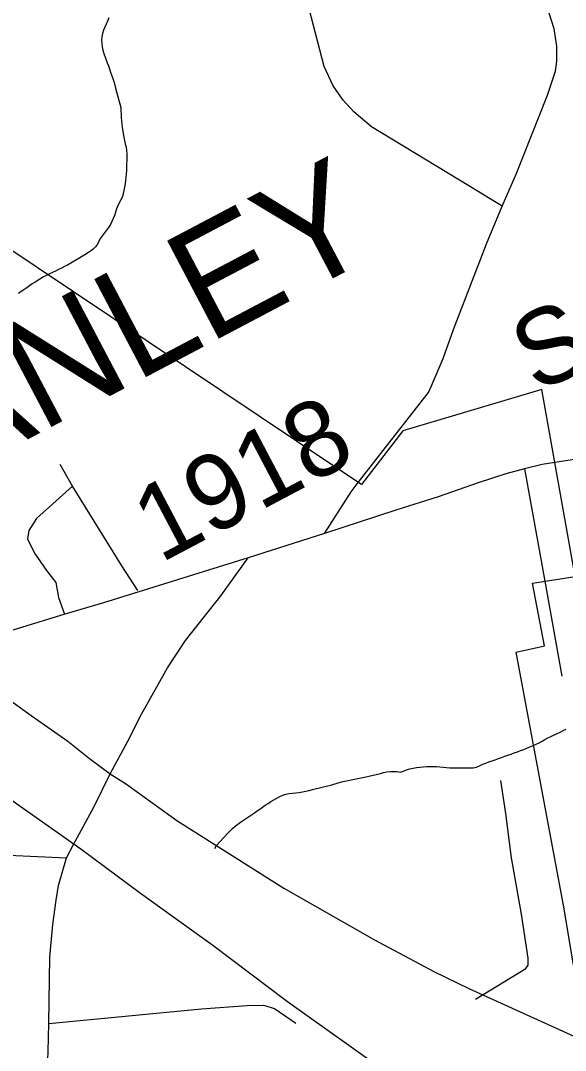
# Model space of a CAD drawing. Extents: x 1379448 to 1382868, y 593769 to 596827.
# Drawn here: x 1379829.3 to 1379935.9, y 595296.5 to 595497.8 of the extents above; entities that cross this region are included whole.
import ezdxf

# ---------------------------------------------------------------- set-up
doc = ezdxf.new("R2010")
doc.units = 0
for name, color, linetype in [('Old_Level_11', 7, 'Continuous'), ('Old_Level_29', 7, 'Continuous'), ('Old_Level_32', 7, 'Continuous'), ('Old_Level_35', 7, 'Continuous'), ('Old_Level_44', 7, 'Continuous'), ('Old_Level_48', 7, 'Continuous'), ('Old_Level_49', 7, 'Continuous'), ('Old_Level_59', 7, 'Continuous'), ('Old_Level_62', 7, 'Continuous'), ('Old_Level_8', 7, 'Continuous'), ('Old_Level_9', 7, 'Continuous')]:
    doc.layers.add(name, color=color, linetype=linetype)

msp = doc.modelspace()

# ---------------------------------------------------------------- linework, layer by layer
at = {"layer": 'Old_Level_29'}
for points in [[(1379811.94, 595374.69), (1379823.59, 595367.52), (1379831.41, 595361.9), (1379838.57, 595356.89), (1379842.83, 595353.5), (1379846.88, 595350.52)], [(1379846.88, 595350.52), (1379850.07, 595348.52), (1379859.88, 595341.4), (1379880.87, 595328.17), (1379898.58, 595318.1), (1379910.18, 595311.88), (1379917.05, 595308.57), (1379941.73, 595297.36)]]:
    msp.add_lwpolyline(points, dxfattribs=at)
at = {"layer": 'Old_Level_32'}
msp.add_line((1379888.82, 595397.52), (1379873.86, 595392.77), dxfattribs=at)
for points in [[(1379923.57, 595461.53), (1379926.3, 595467.79), (1379932.44, 595483.19), (1379933.97, 595487.9), (1379934.26, 595489.83), (1379934.28, 595492.82), (1379933.76, 595496.17), (1379928.2, 595513.67), (1379927.29, 595518.6), (1379926.27, 595525.62), (1379924.52, 595536.46), (1379923.75, 595541.51)], [(1379923.57, 595461.53), (1379917.03, 595465.49), (1379898.01, 595477), (1379894.52, 595479.95), (1379892.42, 595482.24), (1379890.47, 595485.05), (1379888.73, 595488.79), (1379885.86, 595499.84), (1379882.5, 595509.41), (1379879.34, 595515.46), (1379874.98, 595524.63), (1379872.01, 595531.16), (1379871.14, 595532.59), (1379869.97, 595533.81), (1379868.42, 595535.06), (1379866.55, 595535.92), (1379863.91, 595536.76), (1379860.35, 595537.12)], [(1379888.82, 595397.52), (1379894, 595405.65), (1379895.4, 595407.48), (1379909.12, 595425.07), (1379909.74, 595426.4), (1379912.03, 595431.73), (1379914.05, 595437.4), (1379920.48, 595454.16), (1379923.57, 595461.53)], [(1379974.02, 595427.95), (1379963.18, 595422.78), (1379949.17, 595415.99), (1379944.08, 595413.49), (1379940.97, 595412.4), (1379937.25, 595411.89), (1379931.41, 595410.98), (1379927.93, 595410.17)], [(1379927.93, 595410.17), (1379924.3, 595409.16), (1379918.84, 595407.44), (1379911.05, 595404.71), (1379902.75, 595402.06), (1379888.82, 595397.52)], [(1379927.93, 595410.17), (1379931.9, 595388.2), (1379935.26, 595369.6)], [(1379873.86, 595392.77), (1379845.53, 595383.99), (1379837.78, 595381.7), (1379820.5, 595376.43), (1379815.6, 595375.21), (1379811.94, 595374.69)], [(1379846.88, 595350.52), (1379850.32, 595356.94), (1379853.01, 595362.2), (1379858.05, 595371.26), (1379861.6, 595376.58), (1379868.51, 595385.35), (1379873.86, 595392.77)], [(1379839.71, 595336.68), (1379843.64, 595344), (1379846.88, 595350.52)], [(1379831.52, 595285.14), (1379833.61, 595287.99), (1379834.17, 595288.97), (1379834.4, 595289.87), (1379834.55, 595291.52), (1379834.76, 595296.24), (1379834.88, 595301.74), (1379835.05, 595314.69), (1379835.67, 595321.08), (1379836.31, 595325.81), (1379836.78, 595328.71), (1379838.31, 595334.08), (1379839.71, 595336.68)]]:
    msp.add_lwpolyline(points, dxfattribs=at)
at = {"layer": 'Old_Level_35'}
msp.add_line((1379839.48, 595406.77), (1379837.08, 595411.03), dxfattribs=at)
for points in [[(1379839.48, 595406.77), (1379832.44, 595400.47), (1379830.94, 595398.11), (1379830.69, 595396.46), (1379832.09, 595393.67), (1379834.41, 595390.27), (1379836.2, 595387.95), (1379836.73, 595384.99), (1379837.9, 595381.73)], [(1379852.3, 595386.37), (1379849.16, 595391.22), (1379839.48, 595406.77)], [(1379918.36, 595306.49), (1379928.17, 595312.47), (1379928.63, 595313.15), (1379928.67, 595314.51), (1379927.33, 595323.06), (1379925.39, 595334.09), (1379924.28, 595342.75), (1379923.27, 595349.22)], [(1379817.01, 595334.82), (1379821.25, 595334.9), (1379838.31, 595334.08)], [(1379834.88, 595301.74), (1379864.72, 595304.59), (1379873.7, 595305.24), (1379876.89, 595305.31), (1379879, 595304.67), (1379883.22, 595301.77)]]:
    msp.add_lwpolyline(points, dxfattribs=at)
at = {"layer": 'Old_Level_44'}
for points in [[(1379937.5, 595266.13), (1379929.48, 595271.61), (1379920.39, 595278.14), (1379909.32, 595286.12), (1379894, 595297.06), (1379881.57, 595305.96), (1379866.93, 595316.98), (1379852.79, 595327.16), (1379841.11, 595335.81), (1379828.36, 595344.82), (1379813.4, 595355.58), (1379798.11, 595366.81), (1379787.48, 595374.46)], [(1379909.32, 595286.12), (1379894, 595297.06), (1379881.57, 595305.96), (1379866.93, 595316.98), (1379852.79, 595327.16), (1379841.11, 595335.81), (1379828.36, 595344.82)]]:
    msp.add_lwpolyline(points, dxfattribs=at)
at = {"layer": 'Old_Level_48'}
msp.add_lwpolyline([(1379937.54, 595313.11), (1379935.68, 595324.14), (1379926.32, 595374.29), (1379931.87, 595375.52), (1379929.49, 595387.82), (1379937.84, 595389.12), (1379931.29, 595425.64), (1379904.13, 595417.61), (1379896.01, 595407.11), (1379890.61, 595410.69), (1379752.56, 595503.09), (1379773.98, 595520.53), (1379770.04, 595524.52), (1379756.34, 595545.51), (1379753.67, 595549.68), (1379728.08, 595528.98), (1379706.83, 595543.73)], dxfattribs=at)
at = {"layer": 'Old_Level_49'}
msp.add_lwpolyline([(1379937.54, 595313.11), (1379935.68, 595324.14), (1379926.32, 595374.29), (1379931.87, 595375.52), (1379929.49, 595387.82), (1379937.84, 595389.12), (1379931.29, 595425.64), (1379904.13, 595417.61), (1379896.01, 595407.11), (1379890.61, 595410.69), (1379752.56, 595503.09), (1379773.98, 595520.53), (1379770.04, 595524.52), (1379756.34, 595545.51), (1379753.67, 595549.68), (1379728.08, 595528.98), (1379706.83, 595543.73)], dxfattribs=at)
at = {"layer": 'Old_Level_59'}
msp.add_lwpolyline([(1379867.37, 595335.92), (1379867.7, 595336.49), (1379869.91, 595338.9), (1379870.36, 595339.38), (1379870.83, 595339.85), (1379871.31, 595340.29), (1379871.82, 595340.7), (1379872.37, 595341.06), (1379875.07, 595342.88), (1379875.6, 595343.26), (1379876.14, 595343.64), (1379876.68, 595344.02), (1379877.22, 595344.39), (1379877.76, 595344.75), (1379878.32, 595345.1), (1379878.89, 595345.43), (1379879.46, 595345.76), (1379880.04, 595346.08), (1379880.64, 595346.36), (1379881.25, 595346.58), (1379881.88, 595346.69), (1379882.54, 595346.74), (1379883.21, 595346.78), (1379883.86, 595346.89), (1379884.5, 595347.01), (1379885.14, 595347.15), (1379885.78, 595347.29), (1379886.42, 595347.45), (1379890.24, 595348.37), (1379892.13, 595348.93), (1379892.76, 595349.09), (1379893.4, 595349.23), (1379894.04, 595349.37), (1379894.69, 595349.5), (1379895.33, 595349.63), (1379895.98, 595349.76), (1379896.63, 595349.87), (1379899.75, 595350.6), (1379900.37, 595350.8), (1379901.01, 595350.93), (1379901.66, 595350.99), (1379902.33, 595351), (1379902.98, 595350.98), (1379903.63, 595350.88), (1379904.24, 595351.08), (1379904.86, 595351.33), (1379905.49, 595351.52), (1379906.13, 595351.64), (1379906.78, 595351.74), (1379907.43, 595351.82), (1379908.09, 595351.89), (1379908.74, 595351.93), (1379909.4, 595351.96), (1379910.05, 595351.96), (1379910.71, 595351.95), (1379911.37, 595351.92), (1379912.01, 595351.82), (1379912.66, 595351.75), (1379913.32, 595351.73), (1379913.97, 595351.71), (1379914.63, 595351.69), (1379915.29, 595351.69), (1379915.95, 595351.68), (1379916.6, 595351.68), (1379917.26, 595351.69), (1379917.91, 595351.73), (1379918.56, 595351.85), (1379919.15, 595352.12), (1379919.75, 595352.39), (1379920.37, 595352.62), (1379920.98, 595352.84), (1379921.6, 595353.06), (1379922.22, 595353.29), (1379922.84, 595353.5), (1379923.46, 595353.73), (1379924.07, 595353.95), (1379924.69, 595354.17), (1379925.31, 595354.39), (1379925.93, 595354.61), (1379926.54, 595354.84), (1379927.16, 595355.07), (1379927.78, 595355.3), (1379928.39, 595355.54), (1379928.99, 595355.79), (1379929.6, 595356.05), (1379930.19, 595356.32), (1379930.78, 595356.61), (1379931.36, 595356.92), (1379931.94, 595357.24), (1379932.51, 595357.55), (1379933.1, 595357.85), (1379934.29, 595358.41), (1379934.88, 595358.69), (1379935.47, 595358.97), (1379936.06, 595359.25)], dxfattribs=at)
at = {"layer": 'Old_Level_62'}
for points in [[(1379846.6, 595498.3), (1379846.36, 595497.7), (1379846.08, 595497.09), (1379845.79, 595496.5), (1379845.55, 595495.89), (1379845.37, 595495.27), (1379845.24, 595494.62), (1379845.19, 595493.96), (1379845.2, 595493.31), (1379845.29, 595492.66), (1379845.44, 595492.01), (1379845.62, 595491.38), (1379846.26, 595489.55), (1379846.51, 595488.94), (1379846.96, 595487.72), (1379847.38, 595486.49), (1379847.57, 595485.87), (1379847.76, 595485.23), (1379847.93, 595484.6), (1379848.94, 595480.83), (1379848.98, 595480.18), (1379849, 595479.52), (1379849.02, 595478.86), (1379849.06, 595478.2), (1379849.13, 595477.55), (1379849.21, 595476.9), (1379849.51, 595474.98), (1379849.66, 595474.34), (1379849.82, 595473.7), (1379849.97, 595473.06), (1379850.06, 595472.41), (1379850.1, 595471.76), (1379850.11, 595471.1), (1379850.11, 595470.44), (1379850.09, 595469.78), (1379850.06, 595469.13), (1379850.03, 595468.47), (1379849.99, 595467.81), (1379849.94, 595467.16), (1379849.87, 595466.51), (1379849.78, 595465.86), (1379849.65, 595465.21), (1379849.27, 595463.31), (1379848.97, 595462.73), (1379848.64, 595462.16), (1379848.34, 595461.57), (1379848.1, 595460.96), (1379847.88, 595460.34), (1379847.68, 595459.71), (1379847.46, 595459.09), (1379847.21, 595458.48), (1379846.91, 595457.91), (1379846.55, 595457.36), (1379846.16, 595456.83), (1379845.75, 595456.32), (1379845.34, 595455.8), (1379844.97, 595455.26)], [(1379844.97, 595455.26), (1379844.66, 595454.67), (1379844.37, 595454.07), (1379844.02, 595453.53), (1379843.54, 595453.09), (1379843.01, 595452.7), (1379842.44, 595452.35), (1379841.88, 595452.01), (1379838.53, 595449.99), (1379837.95, 595449.69), (1379837.36, 595449.4), (1379836.77, 595449.11), (1379836.17, 595448.83), (1379835.58, 595448.55), (1379834.99, 595448.26), (1379834.4, 595447.97), (1379833.81, 595447.67), (1379832.17, 595446.66), (1379831.62, 595446.3), (1379831.07, 595445.92), (1379830.54, 595445.55), (1379830, 595445.17), (1379829.46, 595444.8), (1379828.91, 595444.44)]]:
    msp.add_lwpolyline(points, dxfattribs=at)

# ---------------------------------------------------------------- texts
at = {"layer": 'Old_Level_11'}
msp.add_text('Sandy Ford Rd.', height=14.7638, rotation=25.8015, dxfattribs=at).set_placement((1379930.21, 595424.88))
at = {"layer": 'Old_Level_32'}
msp.add_text('VICINITY MAP SHOWING LOCATION OF PROJECT B-4118', height=18, rotation=27.7977, dxfattribs=at).set_placement((1379828.68, 595001.39))
at = {"layer": 'Old_Level_8'}
msp.add_text('1918', height=14.764, rotation=27.7977, dxfattribs=at).set_placement((1379856.66, 595391.62))
at = {"layer": 'Old_Level_9'}
msp.add_text('STANLEY', height=21.653, rotation=27.7977, dxfattribs=at).set_placement((1379783.45, 595390.97))

doc.saveas('drawing.dxf')
